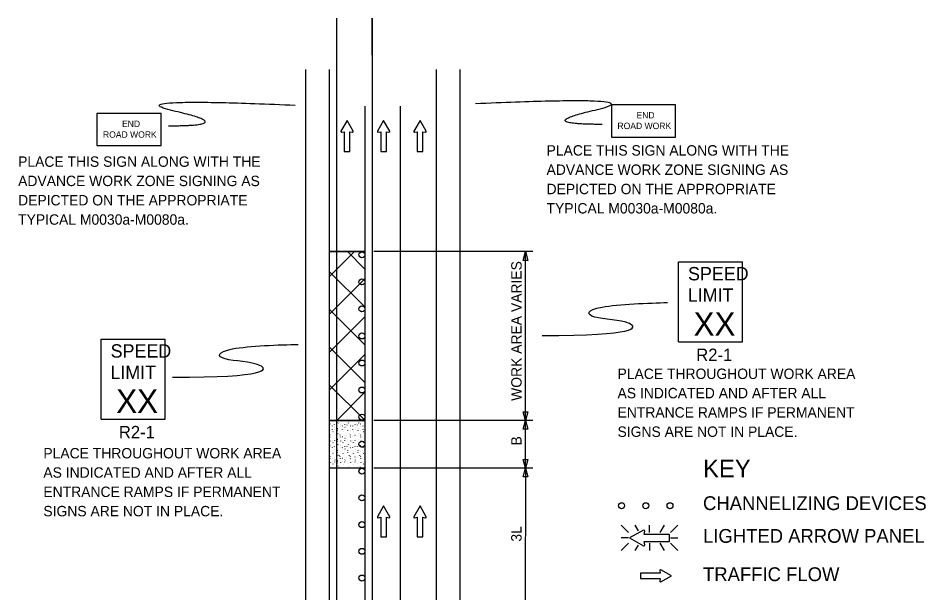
# Model space of a CAD drawing. Extents: x 16782 to 19504, y 6935 to 8243.
# Drawn here: x 16782 to 17393, y 7856 to 8243 of the extents above; entities that cross this region are included whole.
import ezdxf

# ---------------------------------------------------------------- set-up
doc = ezdxf.new("R2010")
doc.units = 0
for name, color, linetype in [('ALI_LEGAL_EX', 7, 'Continuous'), ('MT_SCRATCH_LEVEL_E', 7, 'Continuous'), ('PAVT_EDGE_EX', 7, 'Continuous'), ('TRAFFIC_SIGNS_PR', 7, 'Continuous'), ('TYPICAL_TEXT_DIMEN_EX', 7, 'Continuous'), ('TYPICAL_TEXT_DIMEN_PR', 7, 'Continuous')]:
    doc.layers.add(name, color=color, linetype=linetype)

msp = doc.modelspace()

# ---------------------------------------------------------------- linework, layer by layer
at = {"layer": 'ALI_LEGAL_EX'}
for p, q in [((16995.95, 8243.16), (16995.95, 7425.02)), ((17019.95, 8243.16), (17019.95, 7425.02))]:
    msp.add_line(p, q, dxfattribs=at)
for points in [[(17019.95, 8218.16), (17019.95, 8243.16)], [(17015.15, 8183.87), (17015.15, 8158.87)], [(17039.15, 8158.87), (17039.15, 8183.87)], [(17015.15, 8083.87), (17015.15, 8058.87)], [(17039.15, 8058.87), (17039.15, 8083.87)], [(17039.15, 7958.87), (17039.15, 7983.87)], [(17015.15, 7983.78), (17015.15, 7958.78)], [(17015.15, 7883.25), (17015.15, 7858.25)], [(17039.15, 7858.87), (17039.15, 7883.87)]]:
    msp.add_lwpolyline(points, dxfattribs=at)
at = {"layer": 'MT_SCRATCH_LEVEL_E'}
for p, q in [((17003.12, 8174.22), (16999.01, 8166.98)), ((17007.27, 8166.98), (17003.12, 8174.22)), ((17027.68, 8174.22), (17023.57, 8166.98)), ((17031.83, 8166.98), (17027.68, 8174.22)), ((17052.24, 8174.22), (17048.13, 8166.98)), ((17056.39, 8166.98), (17052.24, 8174.22)), ((16999.49, 8166.3), (17001.27, 8166.61)), ((17001.27, 8166.61), (17001.27, 8153.36)), ((17005.01, 8153.36), (17005.01, 8166.61)), ((17005.01, 8166.61), (17006.79, 8166.3)), ((17024.05, 8166.3), (17025.83, 8166.61)), ((17025.83, 8166.61), (17025.83, 8153.36)), ((17029.57, 8153.36), (17029.57, 8166.61)), ((17029.57, 8166.61), (17031.35, 8166.3)), ((17048.61, 8166.3), (17050.39, 8166.61)), ((17050.39, 8166.61), (17050.39, 8153.36)), ((17054.13, 8153.36), (17054.13, 8166.61)), ((17054.13, 8166.61), (17055.91, 8166.3)), ((17001.27, 8153.36), (17005.01, 8153.36)), ((17025.83, 8153.36), (17029.57, 8153.36)), ((17050.39, 8153.36), (17054.13, 8153.36)), ((17027.68, 7914.58), (17023.57, 7907.34)), ((17031.83, 7907.34), (17027.68, 7914.58)), ((17052.24, 7914.58), (17048.13, 7907.34)), ((17056.39, 7907.34), (17052.24, 7914.58)), ((17024.05, 7906.65), (17025.83, 7906.97)), ((17025.83, 7906.97), (17025.83, 7893.71)), ((17029.57, 7893.71), (17029.57, 7906.97)), ((17029.57, 7906.97), (17031.35, 7906.65)), ((17048.61, 7906.65), (17050.39, 7906.97)), ((17050.39, 7906.97), (17050.39, 7893.71)), ((17054.13, 7893.71), (17054.13, 7906.97)), ((17054.13, 7906.97), (17055.91, 7906.65)), ((17025.83, 7893.71), (17029.57, 7893.71)), ((17050.39, 7893.71), (17054.13, 7893.71)), ((17214.02, 7869.41), (17200.76, 7869.41)), ((17200.76, 7869.41), (17200.76, 7865.66)), ((17213.7, 7871.18), (17214.02, 7869.41)), ((17221.63, 7867.56), (17214.39, 7871.67)), ((17200.76, 7865.66), (17214.02, 7865.66)), ((17214.02, 7865.66), (17213.7, 7863.89)), ((17214.39, 7863.41), (17221.63, 7867.56))]:
    msp.add_line(p, q, dxfattribs=at)
for centre, start, end in [((16999.42, 8166.76), 150.42484, 279.96381), ((17006.86, 8166.76), 260.03619, 29.77312), ((17023.98, 8166.76), 150.42484, 279.96381), ((17031.42, 8166.76), 260.03619, 29.77312), ((17048.54, 8166.76), 150.42484, 279.96381), ((17055.98, 8166.76), 260.03619, 29.77312), ((17023.98, 7907.11), 150.42484, 279.96381), ((17031.42, 7907.11), 260.03619, 29.77312), ((17048.54, 7907.11), 150.42484, 279.96381), ((17055.98, 7907.11), 260.03619, 29.77312), ((17214.16, 7871.26), 60.42484, 189.96381), ((17214.16, 7863.82), 170.03619, 299.77312)]:
    msp.add_arc(centre, 0.463, start, end, dxfattribs=at)
at = {"layer": 'PAVT_EDGE_EX'}
for p, q in [((16975.15, 8208.67), (16975.15, 7354.69)), ((16991.15, 8208.67), (16991.15, 7354.69)), ((17063.15, 8208.67), (17063.15, 7354.69)), ((17079.15, 8208.67), (17079.15, 7354.69)), ((17015.15, 8183.87), (17015.15, 7354.69)), ((17039.15, 7358.87), (17039.15, 8183.87)), ((16991.15, 8085.88), (17015.15, 8085.88)), ((16991.15, 8068.98), (17008.05, 8085.88)), ((17015.24, 8085.88), (16991.24, 8085.88)), ((17015.15, 8074.07), (17003.34, 8085.88)), ((17015.15, 8048.61), (16991.15, 8072.61)), ((16991.15, 8043.53), (17015.15, 8067.53)), ((17015.15, 8023.15), (16991.15, 8047.15)), ((16991.15, 8018.07), (17015.15, 8042.07)), ((17015.15, 7997.7), (16991.15, 8021.7)), ((16991.15, 7992.61), (17015.15, 8016.61)), ((17015.24, 7972.15), (16991.15, 7996.24)), ((16996.15, 7972.15), (17015.15, 7991.16)), ((17015.15, 7972.15), (16991.15, 7972.15)), ((17015.24, 7972.15), (16991.24, 7972.15)), ((16991.24, 7972.15), (17015.24, 7972.15)), ((16993.65, 7971.8), (16993.6, 7971.91)), ((17000.54, 7971.8), (17000.49, 7971.91)), ((17007.43, 7971.8), (17007.37, 7971.91)), ((17014.31, 7971.8), (17014.26, 7971.91)), ((17015.24, 7972.15), (17015.24, 7972.15)), ((16991.55, 7968.33), (16991.5, 7968.26)), ((16991.63, 7969.6), (16991.58, 7969.72)), ((16991.75, 7965.69), (16991.74, 7965.57)), ((16993.03, 7966.26), (16992.98, 7966.19)), ((16993.08, 7968.47), (16993.03, 7968.4)), ((16994.7, 7969.3), (16994.65, 7969.42)), ((16994.83, 7966.01), (16994.78, 7966.13)), ((16994.87, 7967.41), (16994.82, 7967.34)), ((16996.15, 7969.15), (16996.1, 7969.07)), ((16996.8, 7966.54), (16996.75, 7966.66)), ((16997.02, 7970.53), (16996.97, 7970.45)), ((16997.76, 7970.56), (16997.7, 7970.48)), ((16998.44, 7968.33), (16998.39, 7968.26)), ((16998.52, 7969.6), (16998.47, 7969.72)), ((16998.64, 7965.69), (16998.63, 7965.57)), ((16999.92, 7966.26), (16999.87, 7966.19)), ((16999.97, 7968.47), (16999.92, 7968.4)), ((17001.59, 7969.3), (17001.54, 7969.42)), ((17001.72, 7966.01), (17001.67, 7966.13)), ((17001.76, 7967.41), (17001.71, 7967.34)), ((17003.04, 7969.15), (17002.99, 7969.07)), ((17003.69, 7966.54), (17003.63, 7966.66)), ((17003.9, 7970.53), (17003.85, 7970.45)), ((17004.64, 7970.56), (17004.59, 7970.48)), ((17005.33, 7968.33), (17005.28, 7968.26)), ((17005.41, 7969.6), (17005.35, 7969.72)), ((17005.53, 7965.69), (17005.51, 7965.57)), ((17006.81, 7966.26), (17006.76, 7966.19)), ((17006.86, 7968.47), (17006.81, 7968.4)), ((17008.47, 7969.3), (17008.42, 7969.42)), ((17008.6, 7966.01), (17008.55, 7966.13)), ((17008.65, 7967.41), (17008.6, 7967.34)), ((17009.92, 7969.15), (17009.87, 7969.07)), ((17010.57, 7966.54), (17010.52, 7966.66)), ((17010.79, 7970.53), (17010.74, 7970.45)), ((17011.53, 7970.56), (17011.48, 7970.48)), ((17012.21, 7968.33), (17012.16, 7968.26)), ((17012.29, 7969.6), (17012.24, 7969.72)), ((17012.41, 7965.69), (17012.4, 7965.57)), ((17013.69, 7966.26), (17013.64, 7966.19)), ((17013.74, 7968.47), (17013.69, 7968.4)), ((16991.55, 7961.05), (16991.5, 7960.97)), ((16991.63, 7962.31), (16991.58, 7962.43)), ((16993.08, 7961.19), (16993.03, 7961.11)), ((16993.65, 7964.51), (16993.6, 7964.63)), ((16994.7, 7962.02), (16994.65, 7962.13)), ((16994.87, 7960.13), (16994.82, 7960.05)), ((16996.15, 7961.86), (16996.1, 7961.79)), ((16996.61, 7965.34), (16996.56, 7965.27)), ((16996.8, 7959.26), (16996.75, 7959.38)), ((16997.02, 7963.24), (16996.97, 7963.17)), ((16997.76, 7963.27), (16997.7, 7963.2)), ((16998.44, 7961.05), (16998.39, 7960.97)), ((16998.52, 7962.31), (16998.47, 7962.43)), ((16999.97, 7961.19), (16999.92, 7961.11)), ((17000.54, 7964.51), (17000.49, 7964.63)), ((17001.59, 7962.02), (17001.54, 7962.13)), ((17001.76, 7960.13), (17001.71, 7960.05)), ((17003.04, 7961.86), (17002.99, 7961.79)), ((17003.5, 7965.34), (17003.44, 7965.27)), ((17003.69, 7959.26), (17003.63, 7959.38)), ((17003.9, 7963.24), (17003.85, 7963.17)), ((17004.64, 7963.27), (17004.59, 7963.2)), ((17005.33, 7961.05), (17005.28, 7960.97)), ((17005.41, 7962.31), (17005.35, 7962.43)), ((17006.86, 7961.19), (17006.81, 7961.11)), ((17007.43, 7964.51), (17007.37, 7964.63)), ((17008.47, 7962.02), (17008.42, 7962.13)), ((17008.65, 7960.13), (17008.6, 7960.05)), ((17009.92, 7961.86), (17009.87, 7961.79)), ((17010.38, 7965.34), (17010.33, 7965.27)), ((17010.57, 7959.26), (17010.52, 7959.38)), ((17010.79, 7963.24), (17010.74, 7963.17)), ((17011.53, 7963.27), (17011.48, 7963.2)), ((17012.21, 7961.05), (17012.16, 7960.97)), ((17012.29, 7962.31), (17012.24, 7962.43)), ((17013.74, 7961.19), (17013.69, 7961.11)), ((17014.31, 7964.51), (17014.26, 7964.63)), ((16991.55, 7953.76), (16991.5, 7953.69)), ((16991.63, 7955.03), (16991.58, 7955.15)), ((16991.75, 7958.4), (16991.74, 7958.29)), ((16993.03, 7958.98), (16992.98, 7958.9)), ((16993.08, 7953.9), (16993.03, 7953.83)), ((16993.65, 7957.23), (16993.6, 7957.34)), ((16994.7, 7954.73), (16994.65, 7954.85)), ((16994.83, 7958.73), (16994.78, 7958.85)), ((16996.15, 7954.58), (16996.1, 7954.5)), ((16996.61, 7958.06), (16996.56, 7957.98)), ((16997.02, 7955.96), (16996.97, 7955.88)), ((16997.76, 7955.99), (16997.7, 7955.91)), ((16998.44, 7953.76), (16998.39, 7953.69)), ((16998.52, 7955.03), (16998.47, 7955.15)), ((16998.64, 7958.4), (16998.63, 7958.29)), ((16999.92, 7958.98), (16999.87, 7958.9)), ((16999.97, 7953.9), (16999.92, 7953.83)), ((17000.54, 7957.23), (17000.49, 7957.34)), ((17001.59, 7954.73), (17001.54, 7954.85)), ((17001.72, 7958.73), (17001.67, 7958.85)), ((17003.04, 7954.58), (17002.99, 7954.5)), ((17003.5, 7958.06), (17003.44, 7957.98)), ((17003.9, 7955.96), (17003.85, 7955.88)), ((17004.64, 7955.99), (17004.59, 7955.91)), ((17005.33, 7953.76), (17005.28, 7953.69)), ((17005.41, 7955.03), (17005.35, 7955.15)), ((17005.53, 7958.4), (17005.51, 7958.29)), ((17006.81, 7958.98), (17006.76, 7958.9)), ((17006.86, 7953.9), (17006.81, 7953.83)), ((17007.43, 7957.23), (17007.37, 7957.34)), ((17008.47, 7954.73), (17008.42, 7954.85)), ((17008.6, 7958.73), (17008.55, 7958.85)), ((17009.92, 7954.58), (17009.87, 7954.5)), ((17010.38, 7958.06), (17010.33, 7957.98)), ((17010.79, 7955.96), (17010.74, 7955.88)), ((17011.53, 7955.99), (17011.48, 7955.91)), ((17012.21, 7953.76), (17012.16, 7953.69)), ((17012.29, 7955.03), (17012.24, 7955.15)), ((17012.41, 7958.4), (17012.4, 7958.29)), ((17013.69, 7958.98), (17013.64, 7958.9)), ((17013.74, 7953.9), (17013.69, 7953.83)), ((17014.31, 7957.23), (17014.26, 7957.34)), ((16991.63, 7947.74), (16991.58, 7947.86)), ((16991.75, 7951.12), (16991.74, 7951)), ((16993.03, 7951.69), (16992.98, 7951.62)), ((16993.65, 7949.94), (16993.6, 7950.06)), ((16994.7, 7947.45), (16994.65, 7947.56)), ((16994.83, 7951.44), (16994.78, 7951.56)), ((16994.87, 7952.84), (16994.82, 7952.77)), ((16996.15, 7947.3), (16996.1, 7947.22)), ((16996.61, 7950.78), (16996.56, 7950.7)), ((16996.8, 7951.97), (16996.75, 7952.09)), ((16997.02, 7948.68), (16996.97, 7948.6)), ((16997.76, 7948.7), (16997.7, 7948.63)), ((16998.52, 7947.74), (16998.47, 7947.86)), ((16998.64, 7951.12), (16998.63, 7951)), ((16999.92, 7951.69), (16999.87, 7951.62)), ((17000.54, 7949.94), (17000.49, 7950.06)), ((17001.59, 7947.45), (17001.54, 7947.56)), ((17001.72, 7951.44), (17001.67, 7951.56)), ((17001.76, 7952.84), (17001.71, 7952.77)), ((17003.04, 7947.3), (17002.99, 7947.22)), ((17003.5, 7950.78), (17003.44, 7950.7)), ((17003.69, 7951.97), (17003.63, 7952.09)), ((17003.9, 7948.68), (17003.85, 7948.6)), ((17004.64, 7948.7), (17004.59, 7948.63)), ((17005.41, 7947.74), (17005.35, 7947.86)), ((17005.53, 7951.12), (17005.51, 7951)), ((17006.81, 7951.69), (17006.76, 7951.62)), ((17007.43, 7949.94), (17007.37, 7950.06)), ((17008.47, 7947.45), (17008.42, 7947.56)), ((17008.6, 7951.44), (17008.55, 7951.56)), ((17008.65, 7952.84), (17008.6, 7952.77)), ((17009.92, 7947.3), (17009.87, 7947.22)), ((17010.38, 7950.78), (17010.33, 7950.7)), ((17010.57, 7951.97), (17010.52, 7952.09)), ((17010.79, 7948.68), (17010.74, 7948.6)), ((17011.53, 7948.7), (17011.48, 7948.63)), ((17012.29, 7947.74), (17012.24, 7947.86)), ((17012.41, 7951.12), (17012.4, 7951)), ((17013.69, 7951.69), (17013.64, 7951.62)), ((17014.31, 7949.94), (17014.26, 7950.06)), ((16991.55, 7946.48), (16991.5, 7946.4)), ((16991.75, 7943.83), (16991.74, 7943.72)), ((16993.03, 7944.41), (16992.98, 7944.33)), ((16993.08, 7946.62), (16993.03, 7946.54)), ((16993.65, 7942.66), (16993.6, 7942.77)), ((16994.83, 7944.16), (16994.78, 7944.28)), ((16994.87, 7945.56), (16994.82, 7945.48)), ((16996.61, 7943.49), (16996.56, 7943.41)), ((16996.8, 7944.69), (16996.75, 7944.81)), ((16997.02, 7941.39), (16996.97, 7941.31)), ((16997.76, 7941.42), (16997.7, 7941.34)), ((16998.44, 7946.48), (16998.39, 7946.4)), ((16998.64, 7943.83), (16998.63, 7943.72)), ((16999.92, 7944.41), (16999.87, 7944.33)), ((16999.97, 7946.62), (16999.92, 7946.54)), ((17000.54, 7942.66), (17000.49, 7942.77)), ((17001.72, 7944.16), (17001.67, 7944.28)), ((17001.76, 7945.56), (17001.71, 7945.48)), ((17003.5, 7943.49), (17003.44, 7943.41)), ((17003.69, 7944.69), (17003.63, 7944.81)), ((17003.9, 7941.39), (17003.85, 7941.31)), ((17004.64, 7941.42), (17004.59, 7941.34)), ((17005.33, 7946.48), (17005.28, 7946.4)), ((17005.53, 7943.83), (17005.51, 7943.72)), ((17006.81, 7944.41), (17006.76, 7944.33)), ((17006.86, 7946.62), (17006.81, 7946.54)), ((17007.43, 7942.66), (17007.37, 7942.77)), ((17008.6, 7944.16), (17008.55, 7944.28)), ((17008.65, 7945.56), (17008.6, 7945.48)), ((17010.38, 7943.49), (17010.33, 7943.41)), ((17010.57, 7944.69), (17010.52, 7944.81)), ((17010.79, 7941.39), (17010.74, 7941.31)), ((17011.53, 7941.42), (17011.48, 7941.34)), ((17012.21, 7946.48), (17012.16, 7946.4)), ((17012.41, 7943.83), (17012.4, 7943.72)), ((17013.69, 7944.41), (17013.64, 7944.33)), ((17013.74, 7946.62), (17013.69, 7946.54)), ((17014.31, 7942.66), (17014.26, 7942.77)), ((17015.15, 7940.1), (16991.24, 7940.1)), ((17015.24, 7940.1), (16991.24, 7940.1)), ((16991.63, 7940.46), (16991.58, 7940.58)), ((16994.7, 7940.16), (16994.65, 7940.28)), ((16998.52, 7940.46), (16998.47, 7940.58)), ((17001.59, 7940.16), (17001.54, 7940.28)), ((17005.41, 7940.46), (17005.35, 7940.58)), ((17008.47, 7940.16), (17008.42, 7940.28)), ((17012.29, 7940.46), (17012.24, 7940.58))]:
    msp.add_line(p, q, dxfattribs=at)
at = {"layer": 'TRAFFIC_SIGNS_PR'}
for p, q in [((17226.26, 8079.08), (17269.46, 8079.08)), ((17226.26, 8025.08), (17226.26, 8079.08)), ((17269.46, 8025.08), (17269.46, 8079.08)), ((16837.4, 8027.04), (16880.6, 8027.04)), ((16837.4, 7973.04), (16837.4, 8027.04)), ((16880.6, 7973.04), (16880.6, 8027.04)), ((17226.26, 8025.08), (17269.46, 8025.08)), ((16837.4, 7973.04), (16880.6, 7973.04)), ((17187.66, 7901.56), (17192.59, 7896.63)), ((17199.42, 7897.74), (17197.22, 7901.57)), ((17206.74, 7896.63), (17206.74, 7901.57)), ((17213.98, 7896.63), (17216.83, 7901.57)), ((17220.89, 7896.63), (17225.83, 7901.57)), ((17192.59, 7893.07), (17187.66, 7893.07)), ((17220.89, 7893.07), (17225.83, 7893.07)), ((17187.66, 7884.59), (17192.59, 7889.52)), ((17197.17, 7884.58), (17199.28, 7888.25)), ((17206.74, 7889.52), (17206.74, 7884.58)), ((17216.87, 7884.58), (17214.02, 7889.52)), ((17220.89, 7889.52), (17225.83, 7884.58))]:
    msp.add_line(p, q, dxfattribs=at)
for points in [[(17181.17, 8163.08), (17224.37, 8163.08), (17224.37, 8184.68), (17181.17, 8184.68)], [(16834.67, 8157.29), (16877.88, 8157.29), (16877.88, 8178.89), (16834.67, 8178.89)]]:
    msp.add_lwpolyline(points, close=True, dxfattribs=at)
for points in [[(17202.67, 7898.35), (17193.38, 7893.07), (17202.67, 7887.75)], [(17203.55, 7888.38), (17203.14, 7890.65), (17220.16, 7890.65), (17220.16, 7895.45), (17203.14, 7895.45), (17203.55, 7897.73)]]:
    msp.add_lwpolyline(points, dxfattribs=at)
for centre in [(17013.14, 8083.76), (17013.14, 8065.54), (17013.14, 8047.33), (17013.14, 8029.11), (17013.14, 8010.9), (17013.14, 7992.69), (17013.14, 7974.47), (17013.14, 7956.26), (17013.14, 7938.04), (17013.14, 7920.04), (17188, 7914.76), (17204.3, 7914.76), (17220.6, 7914.76), (17013.14, 7902.04), (17013.14, 7884.04), (17013.14, 7866.04)]:
    msp.add_circle(centre, 2, dxfattribs=at)
for centre, radius, start, end in [((17202.96, 7897.83), 0.598, 350.73078, 118.89165), ((17202.96, 7888.28), 0.597, 241.48329, 9.95933)]:
    msp.add_arc(centre, radius, start, end, dxfattribs=at)
at = {"layer": 'TYPICAL_TEXT_DIMEN_PR'}
for p, q in [((17128.24, 8085.88), (17021.23, 8085.88)), ((17121.67, 8080.02), (17123.24, 8085.88)), ((17123.24, 7972.15), (17123.24, 8085.88)), ((17123.24, 8085.88), (17124.81, 8080.02)), ((17123.24, 8080.02), (17121.67, 8080.02)), ((17124.81, 8080.02), (17123.24, 8080.02)), ((17123.24, 7972.15), (17121.67, 7978.02)), ((17121.67, 7978.02), (17123.24, 7978.02)), ((17123.24, 7978.02), (17124.81, 7978.02)), ((17124.81, 7978.02), (17123.24, 7972.15)), ((17128.24, 7972.15), (17021.23, 7972.15)), ((17121.67, 7966.29), (17123.24, 7972.15)), ((17123.24, 7940.1), (17123.24, 7972.15)), ((17123.24, 7972.15), (17124.81, 7966.29)), ((17123.24, 7966.29), (17121.67, 7966.29)), ((17124.81, 7966.29), (17123.24, 7966.29)), ((17123.24, 7940.1), (17121.67, 7945.96)), ((17121.67, 7945.96), (17123.24, 7945.96)), ((17123.24, 7945.96), (17124.81, 7945.96)), ((17124.81, 7945.96), (17123.24, 7940.1)), ((17128.24, 7940.1), (17021.23, 7940.1)), ((17121.67, 7934.23), (17123.24, 7940.1)), ((17123.24, 7940.1), (17123.15, 7848.04)), ((17123.24, 7940.1), (17124.81, 7934.23)), ((17123.24, 7934.23), (17121.67, 7934.23)), ((17124.81, 7934.23), (17123.24, 7934.23))]:
    msp.add_line(p, q, dxfattribs=at)
for points, degree in [([(16882.8, 8170.68), (16930.03, 8170.68), (16845.01, 8190.03), (16968.11, 8184.54)], 2), ([(17174.91, 8171.6), (17127.67, 8171.6), (17212.69, 8190.95), (17089.6, 8185.45)], 2), ([(17134.47, 8029.4), (17199.05, 8029.4), (17199.05, 8040.15), (17164.13, 8040.15), (17164.13, 8049.82), (17206.99, 8051.34), (17218.9, 8051.59)], 3), ([(17244.04, 8036.81), (17244.05, 8036.81), (17244.06, 8036.81), (17244.06, 8036.81)], 2), ([(16885.65, 8001.24), (16950.23, 8001.24), (16950.23, 8011.99), (16915.31, 8011.99), (16915.31, 8021.65), (16958.17, 8023.18), (16970.08, 8023.43)], 3), ([(16995.22, 8008.65), (16995.23, 8008.65), (16995.24, 8008.65), (16995.24, 8008.65)], 2)]:
    msp.add_open_spline(points, degree=degree, dxfattribs=at)

# ---------------------------------------------------------------- texts
at = {"layer": 'TRAFFIC_SIGNS_PR'}
for s, height, p in [('END', 4.31, (17198.04, 8175.61)), ('END', 4.31, (16851.55, 8169.82)), ('ROAD WORK', 4.31, (17185.22, 8168.42)), ('ROAD WORK', 4.31, (16838.73, 8162.63)), ('PLACE THIS SIGN ALONG WITH THE', 7, (17137.46, 8150.59)), ('PLACE THIS SIGN ALONG WITH THE', 7, (16781.58, 8143.03)), ('ADVANCE WORK ZONE SIGNING AS', 7, (17137.46, 8137.59)), ('ADVANCE WORK ZONE SIGNING AS', 7, (16781.58, 8130.03)), ('DEPICTED ON THE APPROPRIATE', 7, (17137.46, 8124.59)), ('DEPICTED ON THE APPROPRIATE', 7, (16781.58, 8117.03)), ('TYPICAL M0030a-M0080a.', 7, (17137.46, 8111.59)), ('TYPICAL M0030a-M0080a.', 7, (16781.58, 8104.03)), ('SPEED', 9, (17232.75, 8066.55)), ('LIMIT', 9, (17232.57, 8052.15)), ('XX', 15.785, (17236.51, 8029.31)), ('SPEED', 9, (16843.89, 8014.51)), ('R2-1', 8.37, (17238.27, 8012.21)), ('LIMIT', 9, (16843.71, 8000.11)), ('PLACE THROUGHOUT WORK AREA', 7, (17185.27, 8000.12)), ('XX', 15.785, (16847.65, 7977.27)), ('AS INDICATED AND AFTER ALL', 7, (17185.27, 7987.12)), ('ENTRANCE RAMPS IF PERMANENT', 7, (17185.27, 7974.12)), ('R2-1', 8.37, (16849.41, 7960.17)), ('SIGNS ARE NOT IN PLACE.', 7, (17185.27, 7961.12)), ('PLACE THROUGHOUT WORK AREA', 7, (16798.58, 7946.63)), ('AS INDICATED AND AFTER ALL', 7, (16798.58, 7933.63)), ('ENTRANCE RAMPS IF PERMANENT', 7, (16798.58, 7920.63)), ('SIGNS ARE NOT IN PLACE.', 7, (16798.58, 7907.63))]:
    msp.add_text(s, height=height, dxfattribs=at).set_placement(p)
at = {"layer": 'TYPICAL_TEXT_DIMEN_EX'}
for s, height, p in [('KEY', 12, (17242.84, 7933.87)), ('CHANNELIZING DEVICES', 9.3, (17242.84, 7911.82)), ('LIGHTED ARROW PANEL', 9.3, (17242.84, 7889.77)), ('TRAFFIC FLOW', 9.3, (17242.84, 7863.97))]:
    msp.add_text(s, height=height, dxfattribs=at).set_placement(p)
at = {"layer": 'TYPICAL_TEXT_DIMEN_PR'}
for s, p in [('WORK AREA VARIES', (17120.68, 7985.37)), ('B', (17120.68, 7955.36)), ('3L', (17120.64, 7890.57))]:
    msp.add_text(s, height=7, rotation=90, dxfattribs=at).set_placement(p)

doc.saveas('drawing.dxf')
